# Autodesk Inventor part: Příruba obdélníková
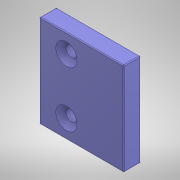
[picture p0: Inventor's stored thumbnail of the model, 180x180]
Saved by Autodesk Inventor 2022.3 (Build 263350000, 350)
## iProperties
Created: 2025-11
Part Number: Příruba obdélníková
Material: Všeobecné
Document SubType Name: Modeling
Designer: Hra42
Density: 1 g/cm^3
Appearance: Výchozí
Author: Hra42
Sending System: SolidWorks 2012
Last Author: Hra42
Last Saved: 2025-11-10
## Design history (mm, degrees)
node "Příruba obdélníková.SLDPRT"
node "Těleso1"
feature "Kuželové zahloubení pro M6 šroubu se zápustnou hlavou plocho"
